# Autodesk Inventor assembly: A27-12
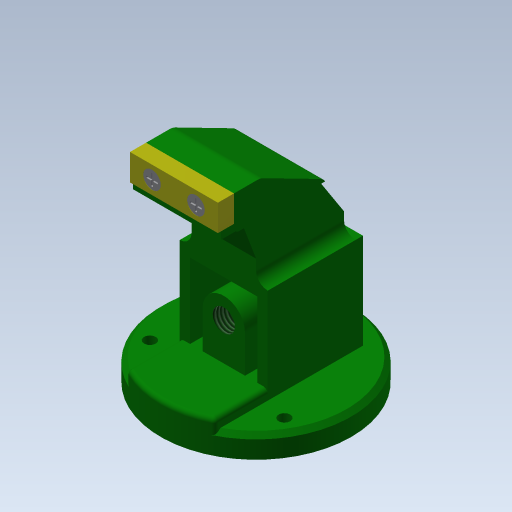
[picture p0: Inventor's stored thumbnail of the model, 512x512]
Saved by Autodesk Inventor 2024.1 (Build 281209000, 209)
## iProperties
Created: 2008-07
Part Number: A27-12
Document SubType Name: Assembly
Designer: y-shimohigashi
Stock Number: A24-12
Author: y-shimohigashi
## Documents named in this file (4)
- C:\Users\h-sato\Desktop\ブログ用モデル\Inventor\図面の作成\A27-12.iam
- C:\Users\h-sato\Desktop\R2024\Inventor2024基礎コース\練習問題\練習問題-27\P27-2ベース.ipt
- C:\Users\h-sato\Desktop\R2024\Inventor2024基礎コース\練習問題\練習問題-27\P27-4締付板.ipt
- C:\Users\h-sato\Desktop\R2024\Inventor2024基礎コース\練習問題\練習問題-27\P27-11ボルト.ipt
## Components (4 placed, 3 different names)
1. P27-2ベース:1
2. P27-4締付板:1 — 挿入:2, 挿入:3
3. P27-11ボルト:1 — 挿入:2
4. P27-11ボルト:2 — 挿入:3
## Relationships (2: Insert 2)
- 挿入:2 [Insert]: P27-4締付板:1 ↔ P27-11ボルト:1
- 挿入:3 [Insert]: P27-4締付板:1 ↔ P27-11ボルト:2
